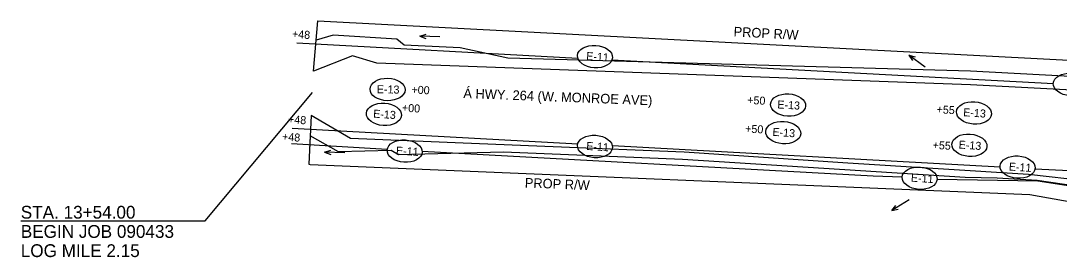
# Model space of a CAD drawing. Extents: x 670673 to 672613, y 705754 to 707185.
# Drawn here: x 670673 to 671322, y 706485 to 706632 of the extents above; entities that cross this region are included whole.
import ezdxf

# ---------------------------------------------------------------- set-up
doc = ezdxf.new("R2010")
doc.units = 0
for name, color, linetype in [('R_Draft', 7, 'Continuous'), ('R_Erosion Clearing Right', 7, 'Continuous'), ('R_Erosion Stage 1', 7, 'Continuous'), ('R_Erosion Stage 2', 7, 'Continuous'), ('R_Flow Arrows Clear and Grub', 7, 'Continuous'), ('R_No Plot', 7, 'Continuous'), ('R_Proposed Sidewalk', 7, 'Continuous')]:
    doc.layers.add(name, color=color, linetype=linetype)

# ---------------------------------------------------------------- blocks, each defined once
blk = doc.blocks.new('FLOW ARROW')
at = {"layer": 'R_Proposed Sidewalk'}
for p, q in [((-1.78, 0.09), (10.79, 0.09)), ((10.79, 0.09), (6.94, 1.49)), ((10.79, 0.09), (6.94, -1.31))]:
    blk.add_line(p, q, dxfattribs=at)

msp = doc.modelspace()

# ---------------------------------------------------------------- linework, layer by layer
at = {"layer": 'R_Draft'}
msp.add_line((670787.98, 706507.42), (670855.02, 706587.48), dxfattribs=at)
msp.add_lwpolyline([(670672.8, 706507.42), (670787.98, 706507.42)], dxfattribs=at)
at = {"layer": 'R_Erosion Clearing Right'}
for p, q in [((670845.36, 706618.56), (671020.89, 706609.09)), ((671042.02, 706607.95), (671317.96, 706593.08)), ((670842.46, 706565.23), (671020.84, 706555.52)), ((671042.48, 706554.34), (671284.66, 706541.16)), ((671306.65, 706539.96), (671588.71, 706524.61))]:
    msp.add_line(p, q, dxfattribs=at)
for centre in [(671031.57, 706609.97), (671328.86, 706592.55), (671031.57, 706553.81), (671295.63, 706540.94)]:
    msp.add_ellipse(centre, major_axis=(10.93, -0.71), ratio=0.638788, dxfattribs=at)
at = {"layer": 'R_Erosion Stage 1'}
for centre, major_axis in [((670901.98, 706589.45), (10.96, -0.25)), ((671152.23, 706579.71), (10.94, -0.62)), ((671268.37, 706574.79), (10.93, -0.76))]:
    msp.add_ellipse(centre, major_axis=major_axis, ratio=0.638788, dxfattribs=at)
at = {"layer": 'R_Erosion Stage 2'}
msp.add_line((671308.3, 706532.17), (671245.34, 706533.28), dxfattribs=at)
for points in [[(670901.77, 706551.95), (670842.03, 706555.58)], [(671223.47, 706534.7), (671205.41, 706535.31), (670923.61, 706550.62)], [(671565.48, 706509.14), (671560.45, 706509.66), (671500.97, 706505.65), (671445.3, 706507.31), (671356.92, 706524.57), (671308.3, 706532.17)]]:
    msp.add_lwpolyline(points, dxfattribs=at)
for centre, major_axis in [((670899.7, 706573.91), (10.93, -0.76)), ((671149.19, 706562.52), (10.93, -0.76)), ((671265.52, 706554.58), (10.93, -0.76)), ((670912.67, 706550.92), (10.93, -0.71)), ((671234.41, 706533.99), (10.93, -0.71))]:
    msp.add_ellipse(centre, major_axis=major_axis, ratio=0.638788, dxfattribs=at)
at = {"layer": 'R_No Plot'}
for points in [[(671532.65, 706578.47), (671266.24, 706592.45), (670895.26, 706605.97), (670879.99, 706610.5), (670855.73, 706600.79), (670858.39, 706632.38), (671562.42, 706595.43)], [(671340.31, 706597.03), (671266.3, 706600.85), (670977.08, 706608.97), (670947.29, 706615.46), (670912.32, 706617.04), (670907.85, 706620.84), (670867.93, 706623.28), (670857.37, 706620.25), (670858.39, 706632.38), (671562.42, 706595.43)], [(671339.28, 706532.09), (671302.4, 706536.23), (671189.63, 706543.4), (671087.39, 706550.19), (671005.35, 706553.54), (670949.22, 706555.83), (670914.13, 706557.26), (670878.88, 706558.9), (670854.28, 706573.13), (670852.69, 706542.75), (670853.67, 706542.5), (671303.32, 706523.91), (671422.37, 706502.64)], [(671359.04, 706525.08), (671307.81, 706532.59), (671282.82, 706534.05), (671262.82, 706534.5), (671086.16, 706545.59), (670974.41, 706550.33), (670908.82, 706548.71), (670904.21, 706551.36), (670871.35, 706550.56), (670853.62, 706560.55), (670852.69, 706542.75), (670853.67, 706542.5), (671303.32, 706523.91), (671422.37, 706502.64)]]:
    msp.add_lwpolyline(points, dxfattribs=at)

# ---------------------------------------------------------------- block references
at = {"layer": 'R_Flow Arrows Clear and Grub', "yscale": -0.9999999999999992}
for p, rotation in [((670932.91, 706622.26), 177.87947866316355), ((671236.31, 706604.4), 143.27853102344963), ((670873.42, 706549.8), 177.87947866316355), ((671226.33, 706519.38), -148.6046867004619)]:
    msp.add_blockref('FLOW ARROW', p, dxfattribs=dict(at, rotation=rotation))

# ---------------------------------------------------------------- texts
at = {"layer": 'R_Draft'}
for s, height, rotation, p in [('PROP R/W', 6, 356.99576, (671118.07, 706622.65)), ('Á HWY. 264 (W. MONROE AVE)', 6, 357.79245, (670949.25, 706584.13)), ('PROP R/W', 6, 357.66918, (670987.64, 706528.22)), ('STA. 13+54.00', 8, 0, (670672.8, 706508.73)), ('BEGIN JOB 090433', 8, 0, (670672.8, 706496.73)), ('LOG MILE 2.15', 8, 0, (670672.8, 706484.73))]:
    msp.add_text(s, height=height, rotation=rotation, dxfattribs=at).set_placement(p)
at = {"layer": 'R_Erosion Clearing Right'}
for s, rotation, p in [('+48', 355.81454, (670842.09, 706621.79)), ('E-11', 356.27884, (671026, 706607.87)), ('+48', 355.81454, (670839.65, 706568.47)), ('E-11', 356.27884, (671026, 706551.71)), ('E-11', 356.27884, (671290.06, 706538.84))]:
    msp.add_text(s, height=4.999, rotation=rotation, dxfattribs=at).set_placement(p)
at = {"layer": 'R_Erosion Stage 1'}
for s, rotation, p in [('E-13', 358.71883, (670895.23, 706587.15)), ('+00', 356.99576, (670916.8, 706586.97)), ('+50', 356.99576, (671126.59, 706580.44)), ('E-13', 356.73762, (671145.41, 706577.64)), ('+55', 356.99576, (671244.92, 706574.59)), ('E-13', 356.02984, (671261.52, 706572.8))]:
    msp.add_text(s, height=4.999, rotation=rotation, dxfattribs=at).set_placement(p)
at = {"layer": 'R_Erosion Stage 2'}
for s, rotation, p in [('E-13', 356.02984, (670892.86, 706571.92)), ('+00', 356.99576, (670910.87, 706575.59)), ('+48', 355.81454, (670835.91, 706557.62)), ('+50', 356.99576, (671125.3, 706562.55)), ('E-13', 356.02984, (671142.34, 706560.53)), ('+55', 356.99576, (671242.44, 706552.32)), ('E-13', 356.02984, (671258.68, 706552.59)), ('E-11', 356.27884, (670907.11, 706548.82)), ('E-11', 356.27884, (671228.84, 706531.89))]:
    msp.add_text(s, height=4.999, rotation=rotation, dxfattribs=at).set_placement(p)

doc.saveas('drawing.dxf')
